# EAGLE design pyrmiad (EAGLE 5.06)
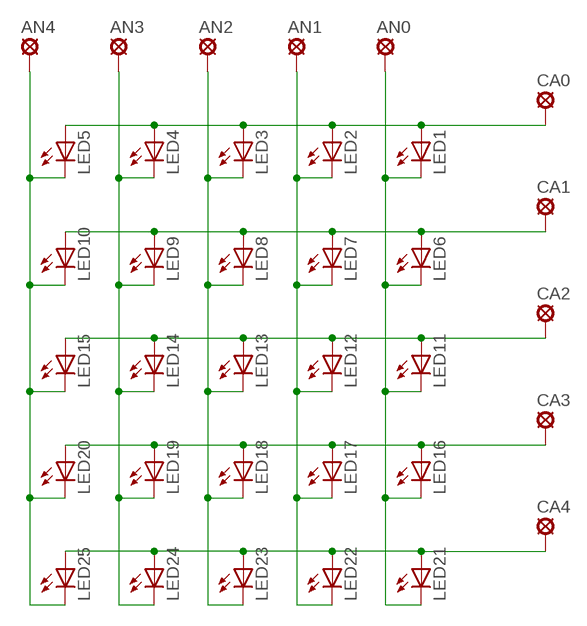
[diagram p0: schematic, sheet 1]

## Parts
AN0  LSP10  [LSP10]
AN1  LSP10  [LSP10]
AN2  LSP10  [LSP10]
AN3  LSP10  [LSP10]
AN4  LSP10  [LSP10]
CA0  LSP10  [LSP10]
CA1  LSP10  [LSP10]
CA2  LSP10  [LSP10]
CA3  LSP10  [LSP10]
CA4  LSP10  [LSP10]
LED1  LED3MM  [LED3MM]
LED2  LED3MM  [LED3MM]
LED3  LED3MM  [LED3MM]
LED4  LED3MM  [LED3MM]
LED5  LED3MM  [LED3MM]
LED6  LED3MM  [LED3MM]
LED7  LED3MM  [LED3MM]
LED8  LED3MM  [LED3MM]
LED9  LED3MM  [LED3MM]
LED10  LED3MM  [LED3MM]
LED11  LED3MM  [LED3MM]
LED12  LED3MM  [LED3MM]
LED13  LED3MM  [LED3MM]
LED14  LED3MM  [LED3MM]
LED15  LED3MM  [LED3MM]
LED16  LED3MM  [LED3MM]
LED17  LED3MM  [LED3MM]
LED18  LED3MM  [LED3MM]
LED19  LED3MM  [LED3MM]
LED20  LED3MM  [LED3MM]
LED21  LED3MM  [LED3MM]
LED22  LED3MM  [LED3MM]
LED23  LED3MM  [LED3MM]
LED24  LED3MM  [LED3MM]
LED25  LED3MM  [LED3MM]

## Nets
N$A0: AN0.MP LED1.K(C) LED6.K(C) LED11.K(C) LED16.K(C) LED21.K(C)
N$A1: AN1.MP LED2.K(C) LED7.K(C) LED12.K(C) LED17.K(C) LED22.K(C)
N$A2: AN2.MP LED3.K(C) LED8.K(C) LED13.K(C) LED18.K(C) LED23.K(C)
N$A3: AN3.MP LED4.K(C) LED9.K(C) LED14.K(C) LED19.K(C) LED24.K(C)
N$A4: AN4.MP LED5.K(C) LED10.K(C) LED15.K(C) LED20.K(C) LED25.K(C)
N$C0: CA0.MP LED1.A LED2.A LED3.A LED4.A LED5.A
N$C1: CA1.MP LED6.A LED7.A LED8.A LED9.A LED10.A
N$C2: CA2.MP LED11.A LED12.A LED13.A LED14.A LED15.A
N$C3: CA3.MP LED16.A LED17.A LED18.A LED19.A LED20.A
N$C4: CA4.MP LED21.A LED22.A LED23.A LED24.A LED25.A

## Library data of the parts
AN0 AN1-AN4 CA0 CA1-CA4 = solpad:LSP10: SOLDER PAD
LED1-LED25 = led:LED: LED

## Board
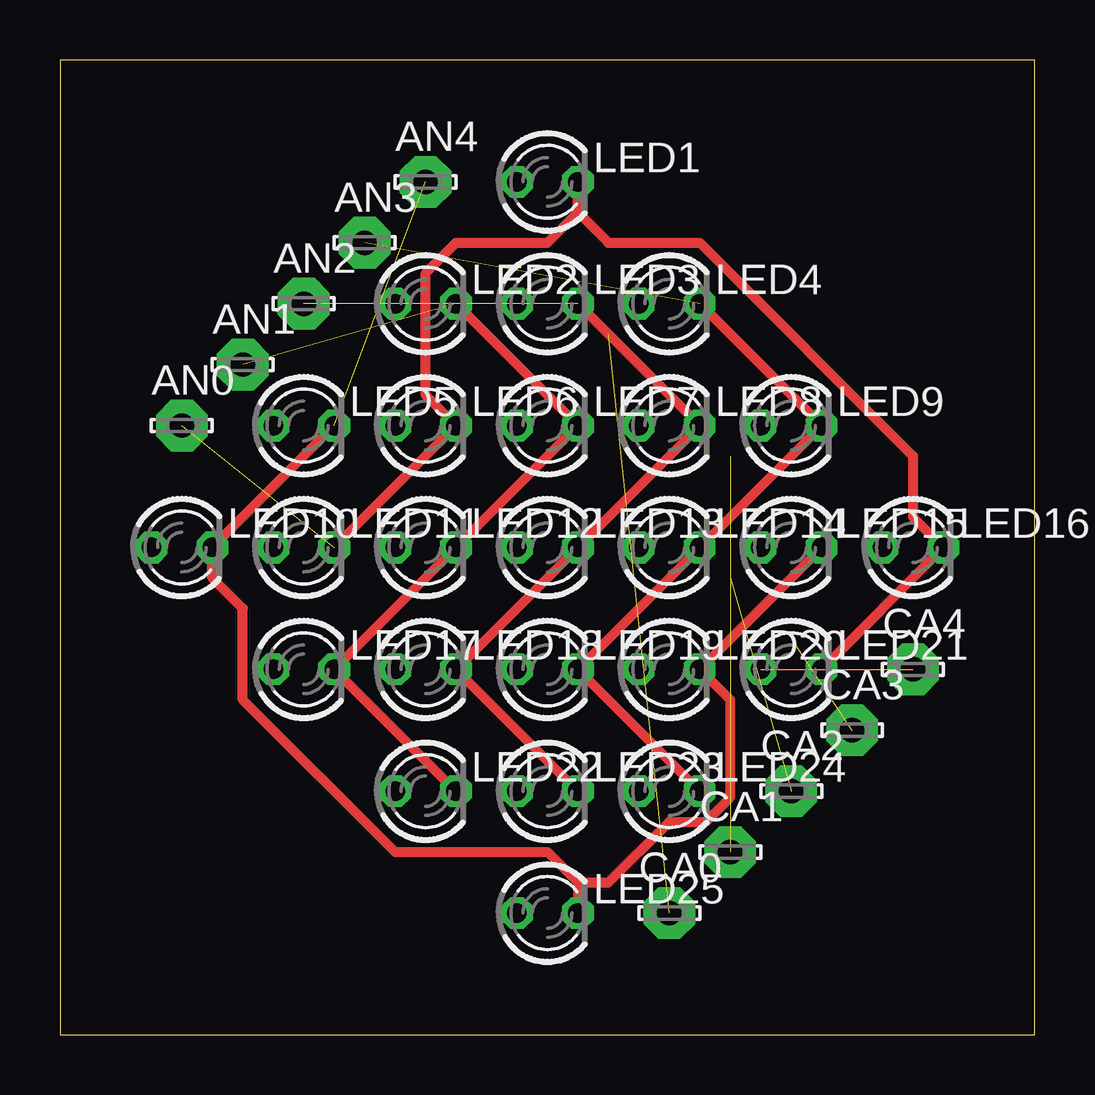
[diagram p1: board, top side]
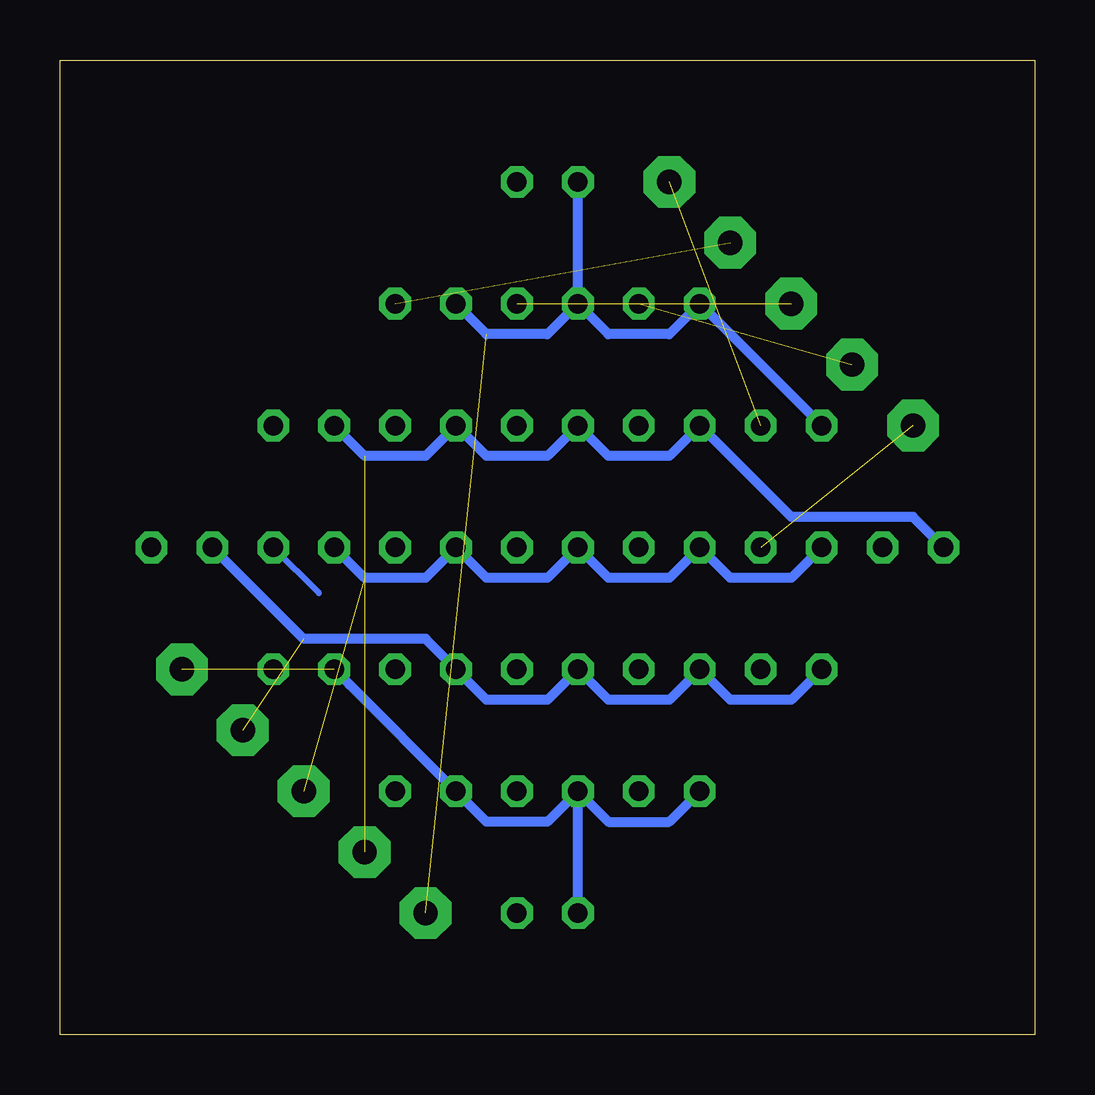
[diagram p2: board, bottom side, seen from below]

Size 40.64 x 40.64 mm. Coordinates in mm from the lower left corner, seen from the top.
Outline: 0,0 40.64,0 40.64,40.64 0,40.64 0,0
Copper layers (1*16): Top 0.035mm / dielectric 1.5mm / Bottom 0.035mm
Design rules "default": minimum track width 10mil, minimum drill 24mil, track to track 8mil, track to pad 8mil, pad to pad 8mil, via to via 8mil, smd to smd 8mil, copper to edge 40mil, drill to drill 8mil, minimum pad ring 10mil, minimum via ring 8mil, stop-mask expansion 4mil, vias tented up to drill 0mil, thermal gap 10mil

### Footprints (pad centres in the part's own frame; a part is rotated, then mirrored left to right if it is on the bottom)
LSP10 = drill 1.016 pad 2.159 octagon: MP 0,0
LED3MM = drill 0.813 octagon: A -1.27,0; K 1.27,0

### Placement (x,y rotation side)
AN0  5.08,25.4 0 top
AN1  7.62,27.94 0 top
AN2  10.16,30.48 0 top
AN3  12.7,33.02 0 top
AN4  15.24,35.56 0 top
CA0  25.4,5.08 0 top
CA1  27.94,7.62 0 top
CA2  30.48,10.16 0 top
CA3  33.02,12.7 0 top
CA4  35.56,15.24 0 top
LED1  20.32,35.56 0 top
LED2  15.24,30.48 0 top
LED3  20.32,30.48 0 top
LED4  25.4,30.48 0 top
LED5  10.16,25.4 0 top
LED6  15.24,25.4 0 top
LED7  20.32,25.4 0 top
LED8  25.4,25.4 0 top
LED9  30.48,25.4 0 top
LED10  5.08,20.32 0 top
LED11  10.16,20.32 0 top
LED12  15.24,20.32 0 top
LED13  20.32,20.32 0 top
LED14  25.4,20.32 0 top
LED15  30.48,20.32 0 top
LED16  35.56,20.32 0 top
LED17  10.16,15.24 0 top
LED18  15.24,15.24 0 top
LED19  20.32,15.24 0 top
LED20  25.4,15.24 0 top
LED21  30.48,15.24 0 top
LED22  15.24,10.16 0 top
LED23  20.32,10.16 0 top
LED24  25.4,10.16 0 top
LED25  20.32,5.08 0 top

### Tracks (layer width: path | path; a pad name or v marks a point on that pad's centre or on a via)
N$A0  (1 unrouted)
  Top 0.406: LED11.K LED6.K 15.24,26.67 15.24,31.75 16.51,33.02 17.14,33.02 20.32,33.02 21.59,34.29 | LED21.K LED16.K 35.56,21.59 35.56,24.13 26.67,33.02 22.86,33.02 21.59,34.29 | 21.59,34.29 LED1.K
N$A1  (1 unrouted)
  Top 0.406: LED22.K LED17.K 12.7,16.51 LED12.K LED7.K LED2.K
N$A2  (1 unrouted)
  Top 0.406: LED23.K LED18.K LED13.K LED8.K LED3.K
N$A3  (1 unrouted)
  Top 0.406: LED24.K LED19.K LED14.K LED9.K LED4.K
N$A4  (1 unrouted)
  Top 0.406: LED5.K 7.62,21.59 LED10.K 6.35,19.05 7.62,17.78 7.62,13.97 13.97,7.62 20.32,7.62 21.59,6.35 | LED15.K LED20.K 27.94,13.97 27.94,9.91 26.92,8.89 25.4,8.89 22.86,6.35 21.59,6.35 | 21.59,6.35 LED25.K
  Bottom 0.254: LED15.K 29.84,18.41
N$C0  (1 unrouted)
  Bottom 0.406: LED3.A LED1.A | LED3.A 17.78,29.21 15.24,29.21 LED2.A LED5.A | LED3.A 20.32,29.21 22.86,29.21 LED4.A
N$C1  (1 unrouted)
  Bottom 0.406: LED9.A 27.94,24.13 25.4,24.13 LED8.A 22.86,24.13 20.32,24.13 LED7.A 17.78,24.13 15.24,24.13 LED6.A 10.16,21.59 5.08,21.59 LED10.A
N$C2  (1 unrouted)
  Bottom 0.406: LED11.A 10.16,19.05 12.7,19.05 LED12.A 15.24,19.05 17.78,19.05 LED13.A 20.32,19.05 22.86,19.05 LED14.A 25.4,19.05 27.94,19.05 LED15.A
N$C3  (1 unrouted)
  Bottom 0.406: LED17.A 10.16,13.97 12.7,13.97 LED18.A 15.24,13.97 17.78,13.97 LED19.A 20.32,13.97 22.86,13.97 LED20.A 25.4,16.51 30.48,16.51 LED16.A
N$C4  (1 unrouted)
  Bottom 0.406: LED22.A 15.24,8.89 17.78,8.89 LED23.A | LED25.A LED23.A | LED23.A 20.32,8.89 22.86,8.89 LED24.A 28.57,14.61 LED21.A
